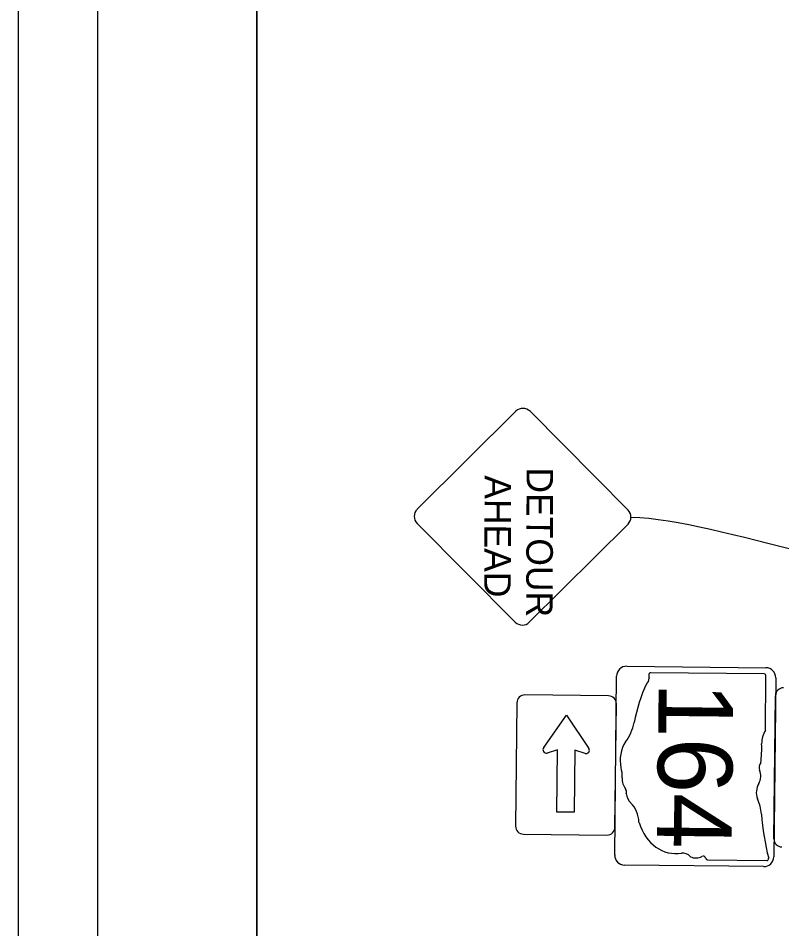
# Model space of a CAD drawing. Extents: x -202 to 1556, y 0 to 676.
# Drawn here: x 0 to 96, y 220.2 to 334.7 of the extents above; entities that cross this region are included whole.
import ezdxf

# ---------------------------------------------------------------- set-up
doc = ezdxf.new("R2010")
doc.units = 0
for name, color, linetype in [('GM_X_Minor_Lake', 7, 'Continuous'), ('GM_X_Minor_Lake_Text', 7, 'Continuous'), ('SH_Border', 7, 'Continuous'), ('SH_Cut_Line', 7, 'Continuous'), ('SH_Data', 7, 'Continuous')]:
    doc.layers.add(name, color=color, linetype=linetype)

msp = doc.modelspace()

# ---------------------------------------------------------------- linework, layer by layer
at = {"layer": 'GM_X_Minor_Lake'}
for p, q in [((93.77, 252.24), (79.54, 252.4)), ((93.94, 245.15), (94.01, 252.01)), ((95.01, 231.51), (95.21, 249.51)), ((86.67, 228.89), (86.66, 228.88)), ((86.66, 228.88), (94.11, 228.8))]:
    msp.add_line(p, q, dxfattribs=at)
for points in [[(50.16, 272.94), (62.58, 285.27)], [(64.35, 285.27), (76.68, 272.85)], [(62.49, 258.76), (50.16, 271.17)], [(76.67, 271.08), (64.26, 258.75)], [(76.5, 253.22), (94, 253.02)], [(74.99, 229.48), (75.24, 251.98)], [(95.24, 251.76), (94.99, 229.26)], [(93.72, 228.02), (76.22, 228.22)]]:
    msp.add_lwpolyline(points, dxfattribs=at)
for centre, radius, start, end in [((63.46, 284.38), 1.25, 44.8108, 134.8108), ((51.04, 272.05), 1.25, 134.8108, 224.8108), ((75.79, 271.97), 1.25, 314.8108, 44.8108), ((63.38, 259.64), 1.25, 224.8108, 314.8108), ((76.49, 251.97), 1.25, 89.359, 179.359), ((93.99, 251.77), 1.25, 359.359, 89.359), ((96.21, 249.5), 1, 89.359, 179.359), ((96.01, 231.5), 1, 179.359, 269.359), ((76.24, 229.47), 1.25, 179.359, 269.359), ((93.74, 229.27), 1.25, 269.359, 359.359)]:
    msp.add_arc(centre, radius, start, end, dxfattribs=at)
for centre, major_axis, start_param, end_param in [((79.51, 252.13), (-0.003, -0.274), 3.00124, 4.508301), ((80.96, 252.07), (-0.02, -2.09), 4.665946, 4.897461), ((93.8, 251.97), (-0.003, -0.271), 1.712693, 3.28349), ((91.39, 242.01), (-0.2, -17.95), 4.195997, 4.488961), ((78.71, 251.67), (-0.008, -0.754), 0.519207, 1.627899), ((73.1, 247.57), (-0.06, -5.62), 0.823519, 1.323587), ((95.57, 243.49), (-0.03, -2.63), 4.042523, 4.731795), ((78.53, 241.43), (-0.04, -3.56), 4.026481, 4.996735), ((85.92, 242.73), (-0.11, -9.45), 1.404758, 1.657858), ((73.59, 239.43), (-0.03, -2.93), 1.495662, 1.94098), ((93.75, 240.49), (-0.009, -0.76), 3.836095, 5.185415), ((92.09, 239.4), (-0.02, -1.58), 0.950623, 2.079405), ((77.44, 239.13), (-0.02, -1.9), 4.691044, 5.507374), ((94.32, 237.33), (-0.02, -1.9), 4.081561, 5.145723), ((76.04, 237.42), (-0.006, -0.535), 1.147584, 2.315152), ((78, 237.63), (-0.02, -2.01), 4.937069, 5.64225), ((75.33, 233.34), (-0.04, -3.4), 1.647645, 2.488434), ((89.47, 234.03), (-0.06, -5), 1.699011, 2.107814), ((82.68, 235.88), (-0.07, -6.22), 5.101752, 6.440018), ((113.25, 236.93), (-0.28, -24.85), 4.814394, 5.042369), ((83.54, 227.98), (-0.02, -1.76), 2.387724, 3.262537), ((85.21, 231.53), (-0.03, -2.42), 5.934695, 6.695948), ((86.12, 228.95), (-0.005, -0.404), 1.883978, 3.671073), ((86.64, 229.16), (-0.003, -0.279), 5.05454, 6.418171), ((94.14, 229.06), (-0.003, -0.261), 6.141152, 7.989035)]:
    msp.add_ellipse(centre, major_axis=major_axis, ratio=0.8, start_param=start_param, end_param=end_param, dxfattribs=at)
at = {"layer": 'GM_X_Minor_Lake_Text'}
for p, q in [((74.21, 249.49), (63.71, 249.61)), ((62.7, 248.62), (62.53, 233.12)), ((75.03, 232.98), (75.2, 248.48)), ((66.09, 243), (68.93, 247.05)), ((68.93, 247.05), (71.73, 242.88)), ((67.79, 242.69), (66.5, 242.3)), ((67.7, 234.88), (67.79, 242.69)), ((69.98, 242.66), (69.89, 234.85)), ((71.26, 242.25), (69.98, 242.66)), ((69.89, 234.85), (67.7, 234.88)), ((63.52, 232.11), (74.02, 231.99))]:
    msp.add_line(p, q, dxfattribs=at)
for centre, radius, start, end in [((63.7, 248.61), 1, 89.359, 179.359), ((74.2, 248.49), 1, 359.359, 89.359), ((66.39, 242.7), 0.417, 134.3494, 286.5636), ((71.39, 242.65), 0.417, 252.1544, 33.9478), ((63.53, 233.11), 1, 179.359, 269.359), ((74.03, 232.99), 1, 269.359, 359.359)]:
    msp.add_arc(centre, radius, start, end, dxfattribs=at)
at = {"layer": 'SH_Border'}
for points in [[(10, 430), (30, 430), (30, 10), (10, 10)], [(30, 430), (670, 430), (670, 10), (30, 10)]]:
    msp.add_lwpolyline(points, close=True, dxfattribs=at)
at = {"layer": 'SH_Cut_Line'}
msp.add_lwpolyline([(0, 0), (680, 0), (680, 440), (0, 440)], close=True, dxfattribs=at)
at = {"layer": 'SH_Data'}
for points in [[(87.45, 355.18), (109.77, 345.09), (127.6, 339.7), (143.95, 339.31), (166.86, 334.83), (177.92, 325.73)], [(77.04, 271.97), (88.48, 271.69), (129.16, 253.62), (142.81, 298.28), (154.55, 318.45), (166.77, 325.92)]]:
    msp.add_open_spline(points, degree=3, dxfattribs=at)

# ---------------------------------------------------------------- texts
at = {"layer": 'GM_X_Minor_Lake'}
for s, height, rotation, p in [('AHEAD', 3.333, 269.8108, (58.64, 277.22)), ('DETOUR', 3.333, 269.8108, (63.92, 278.21)), ('164', 9.375, 269.359, (80.53, 251.24))]:
    msp.add_text(s, height=height, rotation=rotation, dxfattribs=at).set_placement(p)

doc.saveas('drawing.dxf')
